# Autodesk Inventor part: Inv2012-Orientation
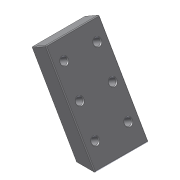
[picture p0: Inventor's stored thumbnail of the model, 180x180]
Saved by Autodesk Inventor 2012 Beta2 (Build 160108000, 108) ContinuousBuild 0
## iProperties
Created: 2011-01
Part Number: Inv2012-Orientation
Material: Default
Document SubType Name: Modeling
Designer: ehttln
Density: 1 g/cm^3
Author: ehttln
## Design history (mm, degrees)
sketch "Sketch1"
  geometry: L1 (-15.905, -14.55)-(7.189, -14.55); L2 (7.189, -14.55)-(-52.811, 89.373); L3 (-52.811, 89.373)-(-70.131, 79.373); L4 (-70.131, 79.373)-(-15.905, -14.55)
  constraints: 8 end point, 1 horizontal, 1 parallel, 1 perpendicular
  dimensions: "d0" = 120 deg angle of L1 L4; "d1" = 120 distance of L1.end L2.end; "d2" = 20 distance between parallel lines of L2 L4
extrude "Extrusion1" new body sketch "Sketch1" stored distance "d3" = 65; taper "d4" = 0 deg
hole "Hole1" diameter "d7" = 8; stored, may be unused: countersink angle "d11" = 90 deg, drill point angle "d13" = 118 deg; dims "d5" = 12.5, "d6" = 25, "d8" = 6, "d9" = 4, "d10" = 2, "d12" = 8
pattern_linear "Rectangular Pattern1" dims "d16" = 40, "d19" = 75
fillet "Fillet1" dims "d20" = 1
body "Solid1"
